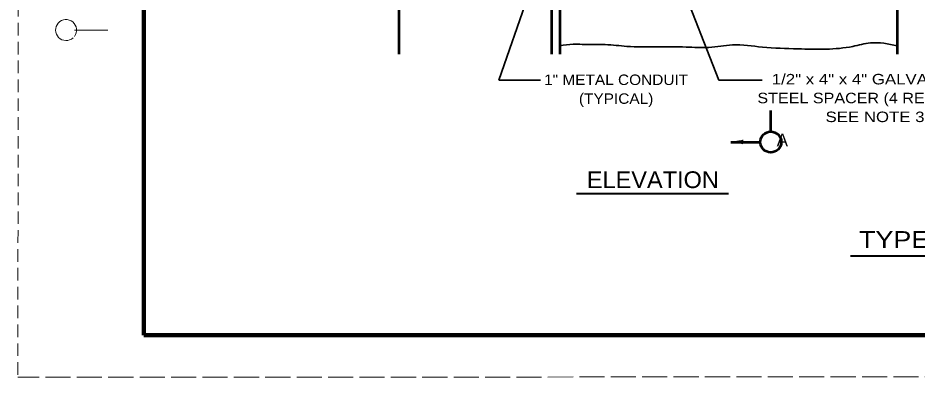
# Model space of a CAD drawing. Extents: x -1 to 679, y 0 to 440.
# Drawn here: x -1.1 to 213.6, y -0.3 to 85.5 of the extents above; entities that cross this region are included whole.
import ezdxf
from ezdxf.enums import TextEntityAlignment as Align

# ---------------------------------------------------------------- set-up
doc = ezdxf.new("R2010")
doc.units = 0
doc.linetypes.add('LONG_DASHED', pattern=[7.5, 6, -1.5])
doc.linetypes.add('MEDIUM_DASHED', pattern=[4.5, 3, -1.5])
doc.layers.add('1', color=7, linetype='Continuous', lineweight=35)
doc.layers.add('61', color=7, linetype='Continuous', lineweight=35)

msp = doc.modelspace()

# ---------------------------------------------------------------- linework, layer by layer
at = {"layer": '1', "linetype": 'MEDIUM_DASHED', "lineweight": 13}
msp.add_line((-0.995, 439.78), (-1.055, -0.26), dxfattribs=at)
at = {"layer": '1'}
for p in [(131.873, 122.636), (123.759, 70.633)]:
    msp.add_line(p, (113.815, 70.633), dxfattribs=at)
at = {"layer": '1', "lineweight": 53}
for p, q in [((89.87, 92.85), (89.87, 76.85)), ((126.37, 93.85), (126.37, 76.85)), ((128.37, 94.1), (128.37, 76.85)), ((208.87, 92.85), (208.87, 76.85)), ((178.714, 58.35), (178.714, 63.35)), ((169.214, 55.85), (176.214, 55.85))]:
    msp.add_line(p, q, dxfattribs=at)
at = {"layer": '1', "lineweight": 40}
for p, q in [((132.313, 43.57), (168.615, 43.57)), ((197.775, 28.692), (304.598, 28.692))]:
    msp.add_line(p, q, dxfattribs=at)
at = {"layer": '1'}
msp.add_lwpolyline([(157.137, 94.1), (166.339, 70.633), (176.631, 70.633)], dxfattribs=at)
at = {"layer": '1', "lineweight": 53}
msp.add_circle((178.714, 55.85), 2.5, dxfattribs=at)
at = {"layer": '1', "lineweight": 40}
for centre, major_axis, ratio, start_param, end_param in [((170.335, 56.062), (-1.756, -0.176), 0.07063, 0.8650754, 3.1424706), ((170.306, 55.574), (-1.786, 0.156), 0.122415, 3.1415927, 5.386832)]:
    msp.add_ellipse(centre, major_axis=major_axis, ratio=ratio, start_param=start_param, end_param=end_param, dxfattribs=at)
at = {"layer": '1'}
msp.add_spline([(128.37, 78.85), (131.561, 79.185), (135.794, 79.102), (139.197, 79.102), (144.343, 78.687), (151.315, 78.604), (158.536, 78.521), (163.932, 78.438), (169.576, 79.019), (176.714, 78.521), (185.18, 78.106), (191.986, 78.023), (198.294, 78.687), (202.528, 79.517), (208.87, 78.85)], degree=3, dxfattribs=at)
at = {"layer": '61', "lineweight": 13}
msp.add_line((12.445, 82.58), (20.425, 82.58), dxfattribs=at)
at = {"layer": '61', "lineweight": 158}
msp.add_line((668.065, 9.74), (29.005, 9.76), dxfattribs=at)
at = {"layer": '61', "linetype": 'LONG_DASHED', "lineweight": 13}
msp.add_line((679.005, -0.24), (-1.055, -0.26), dxfattribs=at)
at = {"layer": '61', "lineweight": 158}
msp.add_lwpolyline([(668.045, 429.78), (29.005, 429.78), (29.005, 9.76)], dxfattribs=at)
at = {"layer": '61', "lineweight": 13}
msp.add_arc((10.423, 82.581), 2.5, 323.13009, 312.31439, dxfattribs=at)

# ---------------------------------------------------------------- texts
at = {"layer": '1'}
for s, width, p in [('1" METAL CONDUIT', 1.1, (141.785, 69.466)), ('1/2" x 4" x 4" GALVANIZED', 1.2, (203.616, 69.611)), ('(TYPICAL)', 1.1, (141.785, 64.966)), ('STEEL SPACER (4 REQUIRED)', 1.15, (203.616, 65.111)), ('SEE NOTE 3', 1.2, (203.616, 60.611))]:
    msp.add_text(s, height=2.5, dxfattribs=dict(at, width=width)).set_placement(p, align=Align.CENTER)
msp.add_text('A', height=3, dxfattribs=at).set_placement((180.148, 54.835))
for s, width, p in [('ELEVATION', 1.05, (134.796, 44.852)), ('TYPE D - INSTALLATION DETAILS', 1.2, (199.797, 30.57))]:
    msp.add_text(s, height=4, dxfattribs=dict(at, width=width)).set_placement(p)

doc.saveas('drawing.dxf')
